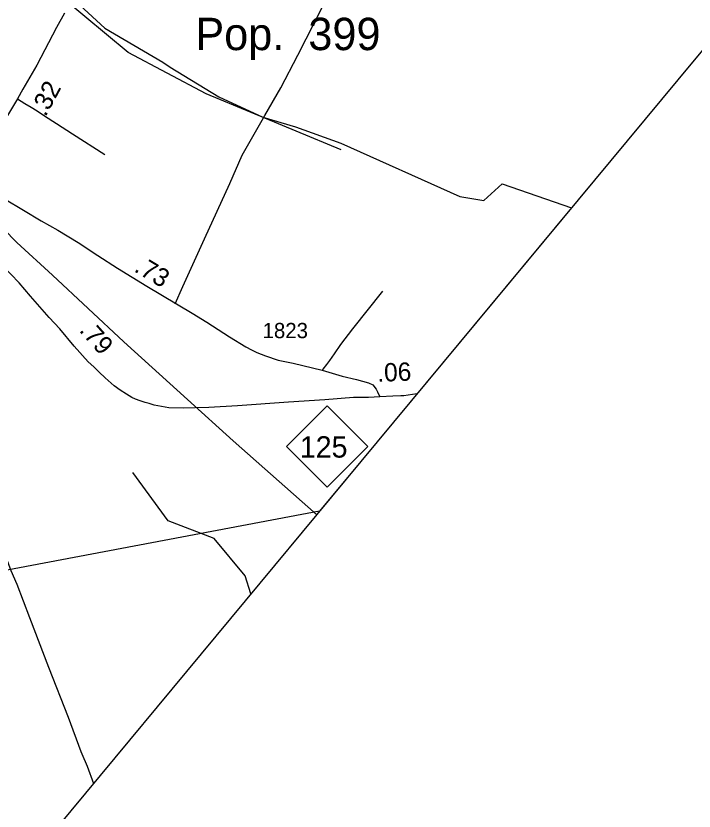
# Model space of a CAD drawing. Extents: x 2290615 to 2522933, y 819489 to 1012715.
# Drawn here: x 2475134 to 2480691, y 828251 to 834764 of the extents above; entities that cross this region are included whole.
import ezdxf

# ---------------------------------------------------------------- set-up
doc = ezdxf.new("R2010")
doc.units = 0
for name, color, linetype in [('Exist Boundary Political City Limit New', 7, 'Continuous'), ('Exist Boundary Political City Limit Old', 7, 'Continuous'), ('Exist Boundary Political CountyLine', 7, 'Continuous'), ('Exist Civil Demographics City Label', 7, 'Continuous'), ('Exist Hydrographic Misc Water Feature', 7, 'Continuous'), ('Exist Road Non-System Type 51', 7, 'Continuous'), ('Exist Road Primary NC Attributed', 7, 'Continuous'), ('Exist Road Primary NC Mileage Hundredths English Label', 7, 'Continuous'), ('Exist Road Primary NC Shield CELL', 7, 'Continuous'), ('Exist Road Primary NC Shield Number Label', 7, 'Continuous'), ('Exist Road Secondary Mileage Hundredths English Label', 7, 'Continuous'), ('Exist Road Secondary Type 51 Attributed', 7, 'Continuous'), ('Exist Road Secondary Type 51 Number Label', 7, 'Continuous'), ('Exist Utilities Electrical Transmission Line', 7, 'Continuous'), ('Map Preparation Boundary City Limit Buffer Line', 7, 'Continuous')]:
    doc.layers.add(name, color=color, linetype=linetype)

msp = doc.modelspace()

# ---------------------------------------------------------------- linework, layer by layer
at = {"layer": 'Exist Boundary Political City Limit New'}
for points in [[(2475658.4, 834852.5), (2475863.1, 834661.9), (2476337.6, 834385.5), (2476397.1, 834344.3), (2476795.8, 834100.2), (2477157.1, 833933.4), (2477424.6, 833855), (2477796.4, 833721.1), (2478772.8, 833285.9), (2478967.1, 833253.1), (2479117.2, 833389.6), (2479685.2, 833191.3)], [(2479685.2, 833191.3), (2477959.5, 831115.5), (2477620.9, 830707.9)], [(2477620.9, 830707.9), (2471531.8, 829558.2)]]:
    msp.add_lwpolyline(points, dxfattribs=at)
at = {"layer": 'Exist Boundary Political City Limit Old'}
for points in [[(2475658.4, 834852.5), (2475863.1, 834661.9), (2476337.6, 834385.5), (2476397.1, 834344.3), (2476795.8, 834100.2), (2477157.1, 833933.4), (2477424.6, 833855), (2477796.4, 833721.1), (2478772.8, 833285.9), (2478967.1, 833253.1), (2479117.2, 833389.6), (2479685.2, 833191.3)], [(2479685.2, 833191.3), (2477959.5, 831115.5), (2477620.9, 830707.9)], [(2477620.9, 830707.9), (2471531.8, 829558.2)]]:
    msp.add_lwpolyline(points, dxfattribs=at)
at = {"layer": 'Exist Boundary Political CountyLine'}
msp.add_lwpolyline([(2490682.1, 847109.5), (2490821, 846558), (2480557.8, 834240.9), (2477959.5, 831115.5), (2474393.8, 826822.4), (2472455.4, 824508.4)], dxfattribs=at)
at = {"layer": 'Exist Hydrographic Misc Water Feature'}
for points in [[(2477799.3, 833667.7), (2476692.3, 834124.9), (2476053.3, 834463.2), (2475521.2, 834907.7), (2475180.2, 834900.3), (2475071.3, 834925.4), (2474751.2, 835135.6), (2474300.3, 835202.6), (2473940.3, 835296.3), (2473632.3, 835326.3), (2473472.3, 835431.5), (2472628.3, 835551.3), (2472153.2, 835577.9), (2471927.3, 835650.7)], [(2477058.8, 830031.1), (2477012.4, 830178.7), (2476758.3, 830483.5), (2476380.4, 830628.9), (2476091.3, 831024.3)]]:
    msp.add_lwpolyline(points, dxfattribs=at)
at = {"layer": 'Exist Road Non-System Type 51'}
for points in [[(2476438.2, 832407), (2476500.8, 832547.2), (2476680.5, 832938.1), (2476886.5, 833390), (2476988.7, 833624.2), (2477174.9, 833949.1), (2477305.1, 834175), (2477443.6, 834442.2), (2477652.1, 834848.7), (2477790, 835105.5)], [(2475148.1, 834084.2), (2475208.3, 834045.5), (2475258.4, 834016.8), (2475308.5, 833986.7), (2475367.2, 833945.2), (2475466, 833882.1), (2475597.7, 833799), (2475864.1, 833628.5)], [(2475148.1, 834084.2), (2475208.3, 834045.5), (2475258.4, 834016.8), (2475308.5, 833986.7), (2475367.2, 833945.2), (2475466, 833882.1), (2475597.7, 833799), (2475864.1, 833628.5)], [(2477643.2, 831862.6), (2477652.5, 831871.5), (2477681.1, 831909.7), (2477707.6, 831942.4), (2477744.7, 831995), (2477797.6, 832071.8), (2477893.8, 832201.2), (2478141.5, 832510.3)], [(2477643.2, 831862.6), (2477652.5, 831871.5), (2477681.1, 831909.7), (2477707.6, 831942.4), (2477744.7, 831995), (2477797.6, 832071.8), (2477893.8, 832201.2), (2478141.5, 832510.3)], [(2474513.8, 832231.5), (2474542.3, 832104.2), (2474561.3, 832034.5), (2474599.1, 831899), (2474632.6, 831797.5), (2474682.9, 831634.2), (2474722.8, 831501), (2474773.5, 831301.7), (2474824.3, 831102.4), (2474866.3, 830951.1), (2474927.5, 830726), (2474961.4, 830592.5), (2474988.6, 830508.8), (2475021.9, 830413.3), (2475073.8, 830274.1), (2475092.6, 830222.4), (2475142.1, 830111.2), (2475246, 829836.7), (2475401.6, 829430.9), (2475563.3, 829021.3), (2475665.2, 828740.9), (2475673.8, 828720.6), (2475716.9, 828619.7), (2475769.3, 828478.6)]]:
    msp.add_lwpolyline(points, dxfattribs=at)
at = {"layer": 'Exist Road Primary NC Attributed'}
for points in [[(2478115.1, 831644), (2478023.4, 831639.7), (2477899.8, 831637.3), (2477666.1, 831619.7), (2477368.4, 831599.6), (2476950.9, 831571.3), (2476715.3, 831557.9), (2476603.7, 831554.5), (2476510.4, 831551.4), (2476388, 831555), (2476325.9, 831564.5), (2476267.2, 831576), (2476226.1, 831588.1), (2476192.5, 831597.4), (2476153, 831610), (2476114.6, 831625.2), (2476084.4, 831638.8), (2476040.7, 831664.6), (2475987.9, 831697.8), (2475939.3, 831735), (2475866.2, 831800.9), (2475816.1, 831846.8), (2475772.6, 831888.6), (2475726.2, 831931.6), (2475612.5, 832059.8), (2475494.5, 832200.1), (2475407.3, 832292.8), (2475252.8, 832468.6), (2475161.3, 832577.1), (2475025.5, 832719.3)], [(2478419.8, 831669.2), (2478312.5, 831652.4), (2478289.2, 831652.4), (2478221.9, 831649.8), (2478115.1, 831644)]]:
    msp.add_lwpolyline(points, dxfattribs=at)
at = {"layer": 'Exist Road Primary NC Shield CELL'}
msp.add_lwpolyline([(2477351.5, 831236.1), (2477684.5, 831569.1), (2478017.5, 831236.1), (2477684.5, 830903.1)], close=True, dxfattribs=at)
at = {"layer": 'Exist Road Secondary Type 51 Attributed'}
for points in [[(2475531.9, 834784.8), (2475466, 834668.8), (2475306.7, 834360.8), (2475190.7, 834162.5), (2475148.1, 834084.2), (2474948.8, 833757.6), (2474875.4, 833636.1), (2474763.4, 833441.2)], [(2475041.8, 833265.3), (2475197.3, 833171.8), (2475340.3, 833085.1), (2475478.9, 833008.1), (2475643.6, 832907.8), (2475806.4, 832801.2), (2475966.7, 832698.9), (2476207.7, 832549.6), (2476577.9, 832328.2), (2476698.2, 832255.2), (2476883, 832136.3), (2477018.2, 832054.3), (2477064.5, 832029), (2477108.8, 832007.6), (2477179.1, 831980.7), (2477281.9, 831943.6), (2477407, 831918.4), (2477643.2, 831862.6), (2477806.5, 831813.8), (2477923.9, 831785.2), (2478023.4, 831758.7), (2478057.8, 831741.5), (2478085, 831707.1), (2478096.4, 831685.6), (2478115.1, 831644)]]:
    msp.add_lwpolyline(points, dxfattribs=at)
at = {"layer": 'Exist Utilities Electrical Transmission Line'}
msp.add_lwpolyline([(2474677.6, 833475.5), (2474714.8, 833408.2), (2474747.6, 833358.7), (2474780.3, 833313.2), (2474862, 833202.7), (2474902.8, 833155.3), (2474972, 833082.3), (2475033, 833019.4), (2475140.7, 832907.1), (2475434.9, 832639.9), (2476017.8, 832093.6), (2476541.2, 831622), (2476914.6, 831284.2), (2477597.6, 830679.8)], dxfattribs=at)
at = {"layer": 'Map Preparation Boundary City Limit Buffer Line'}
for points in [[(2475658.4, 834852.5), (2475863.1, 834661.9), (2476337.6, 834385.5), (2476397.1, 834344.3), (2476795.8, 834100.2), (2477157.1, 833933.4), (2477424.6, 833855), (2477796.4, 833721.1), (2478772.8, 833285.9), (2478967.1, 833253.1), (2479117.2, 833389.6), (2479685.2, 833191.3)], [(2479685.2, 833191.3), (2477959.5, 831115.5), (2477620.9, 830707.9)], [(2477620.9, 830707.9), (2471531.8, 829558.2)]]:
    msp.add_lwpolyline(points, dxfattribs=at)

# ---------------------------------------------------------------- texts
at = {"layer": 'Exist Civil Demographics City Label'}
msp.add_text('Pop.  399', height=265, dxfattribs=at).set_placement((2476604.3, 834483.4))
at = {"layer": 'Exist Road Primary NC Mileage Hundredths English Label'}
for s, rotation, p in [('.79', 311.56067, (2475647.1, 832184.7)), ('.06', 2.20354, (2478097.8, 831766.5))]:
    msp.add_text(s, height=150, rotation=rotation, dxfattribs=at).set_placement(p)
at = {"layer": 'Exist Road Primary NC Shield Number Label'}
msp.add_text('125', height=175, dxfattribs=at).set_placement((2477460.6, 831146.4))
at = {"layer": 'Exist Road Secondary Mileage Hundredths English Label'}
for s, rotation, p in [('.32', 61.49584, (2475376.3, 833932.3)), ('.73', 329.11785, (2476094.8, 832675.4))]:
    msp.add_text(s, height=150, rotation=rotation, dxfattribs=at).set_placement(p)
at = {"layer": 'Exist Road Secondary Type 51 Number Label'}
msp.add_text('1823', height=125, rotation=360, dxfattribs=at).set_placement((2477155.3, 832124.5))

doc.saveas('drawing.dxf')
